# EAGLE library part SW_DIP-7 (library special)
DIP SWITCH
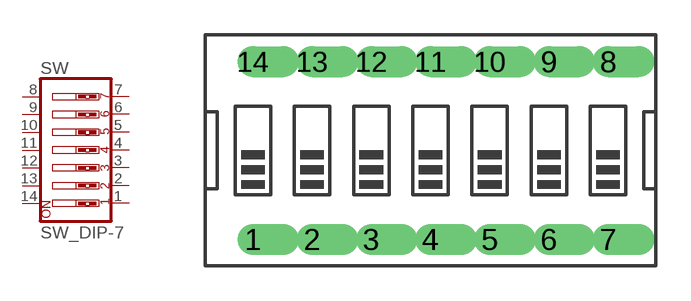
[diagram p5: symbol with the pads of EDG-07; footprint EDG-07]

Designator prefix SW

## SW_DIP-7  [EDG-07]
1  1  pas
2  2  pas
3  3  pas
4  4  pas
5  5  pas
6  6  pas
7  7  pas
8  8  pas
9  9  pas
10  10  pas
11  11  pas
12  12  pas
13  13  pas
14  14  pas

## Footprint EDG-07 (pad centres in mm)
DIP SWITCH
drill 0.813 offset: 1 -7.62,-3.81; 2 -5.08,-3.81; 3 -2.54,-3.81; 4 0,-3.81; 5 2.54,-3.81; 6 5.08,-3.81; 7 7.62,-3.81; 8 7.62,3.81; 9 5.08,3.81; 10 2.54,3.81; 11 0,3.81; 12 -2.54,3.81; 13 -5.08,3.81; 14 -7.62,3.81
